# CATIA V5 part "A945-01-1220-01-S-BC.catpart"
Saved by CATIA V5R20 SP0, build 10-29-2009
Part number: A945-01-1220-01-S-BC
Source: Unknown
Property "ARTICLENO": "A945-01-1220-01-S-BC"
Property "B": "125.000"
Property "BOMINFO": "A945-01-1220-01-S-BC"
Property "CODE": "A945-01-1220-01-S-BC"
Property "D1": "26.000"
Property "D2": "17.500"
Property "D5": "20.000"
Property "D6": "16.000"
Property "H": "57.000"
Property "H1": "44.000"
Property "H2": "60.000"
Property "H3": "28.000"
Property "L1": "200.000"
Property "L2": "25.000"
Property "L3": "0.000"
Property "L4": "150.000"
Property "L5": "55.000"
Property "L6": "95.000"
Property "LINA": "A945-01-1220-01-S-BC"
Property "N": "6.000"
Property "NB": "A945-01-1220-01-S-BC"
Property "NBSYN": "$CODE."
Property "NN": "A945-01"
Property "NT": "v driver sets replaceable inserts pisitive return"
Property "SUPPLIER": "CF"
Property "Z": "85.000"
Bounding box of the stored display mesh (mm): x -669.473 to -511.473, y 748.188 to 833.188, z 0 to 200
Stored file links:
  C:\Users\Utente\Desktop\3D files A945-01\A945-01-1220-01-S-BC.catpart
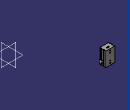
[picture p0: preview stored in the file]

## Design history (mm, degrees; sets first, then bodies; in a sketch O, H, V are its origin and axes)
Body1 "Geometry.1" (main body)
  Solid1 "A945-01-1220-01-S-BC.catpart": solid without history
